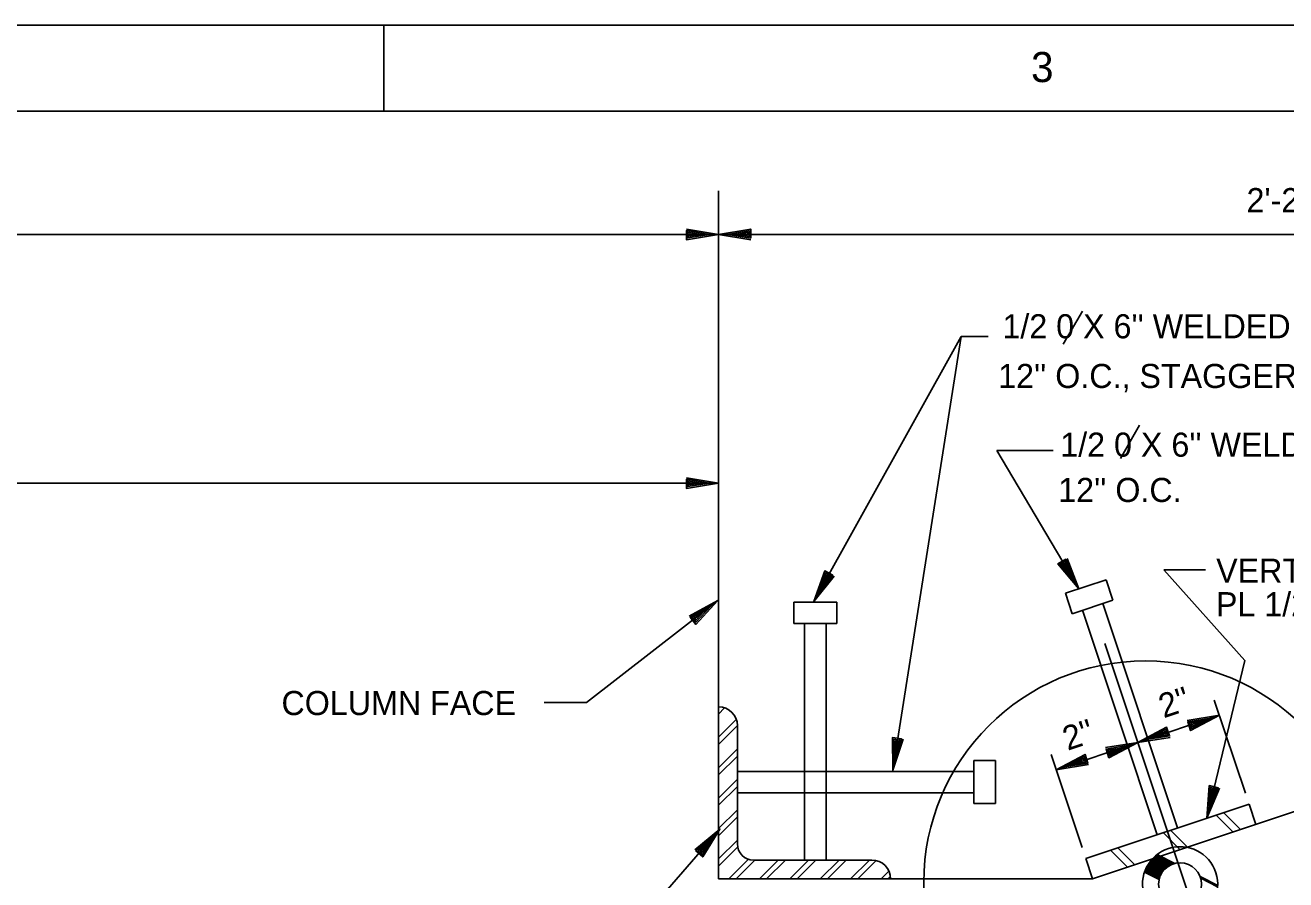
# Model space of a CAD drawing. Extents: x 0.1 to 13.5, y 0.1 to 9.5.
# Drawn here: x 4.972 to 7.414, y 7.802 to 9.458 of the extents above; entities that cross this region are included whole.
import ezdxf

# ---------------------------------------------------------------- set-up
doc = ezdxf.new("R2010")
doc.units = 0
for name, color, linetype in [('Level 1', 7, 'Continuous'), ('Level 13', 7, 'Continuous'), ('Level 25', 7, 'Continuous'), ('Level 3', 7, 'Continuous'), ('Level 36', 7, 'Continuous'), ('Level 44', 7, 'Continuous'), ('Level 50', 7, 'Continuous')]:
    doc.layers.add(name, color=color, linetype=linetype)

msp = doc.modelspace()

# ---------------------------------------------------------------- linework, layer by layer
at = {"layer": 'Level 1'}
for p, q in [((5.6667, 9.2917), (5.6667, 9.4583)), ((7.3359, 7.97), (7.2756, 8.1507)), ((7.1274, 8.0684), (7.2855, 8.1211)), ((6.9693, 8.0157), (7.1274, 8.0684)), ((7.0196, 7.8646), (6.9594, 8.0453))]:
    msp.add_line(p, q, dxfattribs=at)
for points in [[(0.125, 9.4583), (13.4583, 9.4583), (13.4583, 0.125), (0.125, 0.125)], [(0.625, 9.2917), (13.2917, 9.2917), (13.2917, 0.2917), (0.625, 0.2917)]]:
    msp.add_lwpolyline(points, close=True, dxfattribs=at)
at = {"layer": 'Level 13'}
for p, q in [((7.182, 7.825), (7.1529, 7.8399)), ((7.1842, 7.8268), (7.1547, 7.8419)), ((7.1866, 7.8285), (7.1565, 7.8439)), ((7.1893, 7.8301), (7.1584, 7.8458)), ((7.1921, 7.8316), (7.1604, 7.8477)), ((7.1953, 7.8329), (7.1625, 7.8496)), ((7.1989, 7.8339), (7.1648, 7.8514)), ((7.1686, 7.8026), (7.1403, 7.8171)), ((7.1693, 7.8052), (7.1414, 7.8194)), ((7.1701, 7.8077), (7.1421, 7.822)), ((7.1711, 7.8102), (7.1433, 7.8243)), ((7.1722, 7.8125), (7.1443, 7.8267)), ((7.1734, 7.8148), (7.1455, 7.829)), ((7.1748, 7.817), (7.1468, 7.8313)), ((7.1764, 7.8191), (7.1482, 7.8335)), ((7.1781, 7.8212), (7.1497, 7.8356)), ((7.1799, 7.8232), (7.1513, 7.8378)), ((7.2822, 7.7915), (7.248, 7.8089)), ((7.282, 7.7887), (7.2493, 7.8054))]:
    msp.add_line(p, q, dxfattribs=at)
msp.add_circle((7.2093, 7.7936), 0.0417, dxfattribs=at)
msp.add_arc((7.2093, 7.7936), 0.0729, 288, 198, dxfattribs=at)
at = {"layer": 'Level 25'}
for p, q in [((6.3151, 7.8041), (6.3151, 9.1373)), ((2.1636, 9.053), (6.3151, 9.053)), ((8.532, 9.053), (6.3151, 9.053)), ((6.983, 8.84), (7.0201, 8.9042)), ((7.0937, 8.619), (7.1308, 8.6831)), ((6.8544, 8.6339), (6.9631, 8.6339)), ((6.8544, 8.6339), (7.0134, 8.3662)), ((3.1347, 8.5712), (6.3151, 8.5712)), ((7.178, 8.4027), (7.2583, 8.4027)), ((7.178, 8.4027), (7.3344, 8.227)), ((7.0662, 8.3838), (6.9871, 8.3575)), ((7.0793, 8.3443), (7.0662, 8.3838)), ((7.0003, 8.3179), (6.9871, 8.3575)), ((6.4609, 8.2989), (6.4609, 8.3406)), ((6.5443, 8.2989), (6.5443, 8.3406)), ((7.0793, 8.3443), (7.0003, 8.3179)), ((7.2045, 7.9029), (7.0596, 8.3377)), ((7.165, 7.8897), (7.02, 8.3245)), ((6.4818, 7.8406), (6.4818, 8.2989)), ((6.5234, 7.8406), (6.5234, 8.2989)), ((7.3353, 7.4447), (7.0635, 8.2601)), ((7.3344, 8.227), (7.2613, 7.9218)), ((6.3151, 8.1235), (6.3269, 8.1353)), ((6.3151, 8.0785), (6.3494, 8.1128)), ((6.3151, 8.0646), (6.3516, 8.1011)), ((6.3151, 8.0196), (6.3516, 8.056)), ((6.3151, 8.0057), (6.3516, 8.0421)), ((7.7601, 8.0442), (7.0398, 7.8041)), ((6.3516, 8.0124), (6.8099, 8.0124)), ((6.8099, 8.0333), (6.8516, 8.0333)), ((6.3151, 7.9606), (6.3516, 7.9971)), ((6.3151, 7.9468), (6.3516, 7.9832)), ((6.3516, 7.9708), (6.8099, 7.9708)), ((6.3151, 7.9017), (6.3516, 7.9382)), ((6.8099, 7.9499), (6.8516, 7.9499)), ((7.3429, 7.949), (7.0266, 7.8436)), ((7.356, 7.9095), (7.3429, 7.949)), ((6.3151, 7.8878), (6.3516, 7.9243)), ((6.3151, 7.8428), (6.3516, 7.8793)), ((6.3151, 7.8289), (6.3525, 7.8663)), ((6.3353, 7.8041), (6.3734, 7.8422)), ((6.3492, 7.8041), (6.3857, 7.8406)), ((6.3943, 7.8041), (6.4307, 7.8406)), ((6.4081, 7.8041), (6.4446, 7.8406)), ((6.4532, 7.8041), (6.4896, 7.8406)), ((6.4671, 7.8041), (6.5035, 7.8406)), ((6.5121, 7.8041), (6.5486, 7.8406)), ((6.526, 7.8041), (6.5625, 7.8406)), ((6.571, 7.8041), (6.6075, 7.8406)), ((7.0398, 7.8041), (7.0266, 7.8436)), ((6.5849, 7.8041), (6.6201, 7.8393)), ((6.63, 7.8041), (6.6449, 7.8191)), ((6.3151, 7.8041), (7.0398, 7.8041)), ((6.6439, 7.8041), (6.648, 7.8082))]:
    msp.add_line(p, q, dxfattribs=at)
msp.add_circle((7.1424, 7.7968), 0.4297, dxfattribs=at)
at = {"layer": 'Level 3'}
for p, q in [((6.7852, 8.8549), (6.4996, 8.3415)), ((6.508, 8.3566), (6.508, 8.3566)), ((6.3003, 8.3328), (6.3003, 8.3328)), ((6.314, 8.3434), (6.314, 8.3434)), ((6.4996, 8.3415), (6.4996, 8.3415)), ((6.6526, 8.0147), (6.6526, 8.0147)), ((6.6553, 8.0319), (6.6553, 8.0319)), ((6.3177, 7.9005), (6.3177, 7.9005)), ((6.3063, 7.8874), (6.3063, 7.8874))]:
    msp.add_line(p, q, dxfattribs=at)
for points in [[(6.8374, 8.8549), (6.7852, 8.8549), (6.6526, 8.0147)], [(6.5389, 8.3909), (6.4996, 8.3415), (6.5209, 8.401), (6.5363, 8.3924), (6.508, 8.3566), (6.5225, 8.397), (6.5324, 8.3915), (6.5161, 8.3712), (6.5241, 8.3931), (6.5282, 8.3908), (6.5245, 8.3864)], [(5.9772, 8.146), (6.059, 8.146), (6.314, 8.3434)], [(6.2584, 8.3134), (6.314, 8.3434), (6.2711, 8.2971), (6.2603, 8.311), (6.3003, 8.3328), (6.2711, 8.3013), (6.2642, 8.3103), (6.2872, 8.3226), (6.2712, 8.3056), (6.2684, 8.3093), (6.2734, 8.312)], [(6.6726, 8.0747), (6.6526, 8.0147), (6.6521, 8.0779), (6.6696, 8.0752), (6.6553, 8.0319), (6.655, 8.0748), (6.6662, 8.073), (6.6579, 8.0483), (6.6579, 8.0716), (6.6625, 8.0709), (6.6606, 8.0654)], [(6.0169, 7.72), (6.1613, 7.72), (6.3177, 7.9005)], [(6.269, 7.8602), (6.3177, 7.9005), (6.2846, 7.8466), (6.2713, 7.8582), (6.3063, 7.8874), (6.2839, 7.8508), (6.2753, 7.8583), (6.2954, 7.8748), (6.2831, 7.855), (6.2796, 7.8581), (6.284, 7.8617)]]:
    msp.add_lwpolyline(points, dxfattribs=at)
at = {"layer": 'Level 36'}
for p, q in [((6.4609, 8.3406), (6.5443, 8.3406)), ((6.4609, 8.2989), (6.5443, 8.2989)), ((6.3151, 7.8041), (6.3151, 8.1374)), ((6.3516, 8.101), (6.3516, 7.8718)), ((6.8099, 8.0333), (6.8099, 7.9499)), ((6.8516, 8.0333), (6.8516, 7.9499)), ((6.3828, 7.8406), (6.612, 7.8406)), ((6.6484, 7.8041), (6.3151, 7.8041))]:
    msp.add_line(p, q, dxfattribs=at)
for centre, radius, start, end in [((6.3151, 8.101), 0.0365, 0, 90), ((6.3828, 7.8718), 0.0313, 180, 270), ((6.612, 7.8041), 0.0365, 0, 90)]:
    msp.add_arc(centre, radius, start, end, dxfattribs=at)
at = {"layer": 'Level 44'}
for p, q in [((7.3123, 7.8949), (7.2793, 7.9278)), ((7.3264, 7.8996), (7.2935, 7.9326)), ((7.2097, 7.8607), (7.1768, 7.8937)), ((7.2239, 7.8654), (7.1909, 7.8984)), ((7.1214, 7.8313), (7.0884, 7.8642)), ((7.1072, 7.8266), (7.0743, 7.8595))]:
    msp.add_line(p, q, dxfattribs=at)
at = {"layer": 'Level 50'}
for p, q in [((6.2978, 9.053), (6.2978, 9.053)), ((6.3151, 9.053), (6.3151, 9.053)), ((6.3151, 9.053), (6.3151, 9.053)), ((6.3324, 9.053), (6.3324, 9.053)), ((6.2978, 8.5712), (6.2978, 8.5712)), ((6.3151, 8.5712), (6.3151, 8.5712)), ((7.0045, 8.3811), (7.0045, 8.3811)), ((7.0134, 8.3662), (7.0134, 8.3662)), ((7.269, 8.1156), (7.269, 8.1156)), ((7.2855, 8.1211), (7.2855, 8.1211)), ((7.1109, 8.0629), (7.1109, 8.0629)), ((7.1274, 8.0684), (7.1274, 8.0684)), ((7.1274, 8.0684), (7.1274, 8.0684)), ((7.1438, 8.0739), (7.1438, 8.0739)), ((6.9693, 8.0157), (6.9693, 8.0157)), ((6.9857, 8.0212), (6.9857, 8.0212)), ((7.2654, 7.9387), (7.2654, 7.9387)), ((7.2613, 7.9218), (7.2613, 7.9218))]:
    msp.add_line(p, q, dxfattribs=at)
for points in [[(6.2528, 9.0634), (6.3151, 9.053), (6.2528, 9.0427), (6.2528, 9.0604), (6.2978, 9.053), (6.2554, 9.046), (6.2554, 9.0574), (6.2811, 9.053), (6.2581, 9.0494), (6.2581, 9.054), (6.2638, 9.053)], [(6.3774, 9.0427), (6.3151, 9.053), (6.3774, 9.0634), (6.3774, 9.0457), (6.3324, 9.053), (6.3748, 9.06), (6.3748, 9.0487), (6.3491, 9.053), (6.3721, 9.0567), (6.3721, 9.052), (6.3664, 9.053)], [(6.2528, 8.5815), (6.3151, 8.5712), (6.2528, 8.5608), (6.2528, 8.5785), (6.2978, 8.5712), (6.2554, 8.5642), (6.2554, 8.5755), (6.2811, 8.5712), (6.2581, 8.5675), (6.2581, 8.5722), (6.2638, 8.5712)], [(6.9904, 8.4251), (7.0134, 8.3662), (6.9727, 8.4146), (6.9879, 8.4236), (7.0045, 8.3811), (6.9769, 8.414), (6.9866, 8.4198), (6.996, 8.3955), (6.9811, 8.4134), (6.9851, 8.4158), (6.9872, 8.4104)], [(7.2231, 8.1112), (7.2855, 8.1211), (7.2296, 8.0916), (7.224, 8.1083), (7.269, 8.1156), (7.2311, 8.0956), (7.2275, 8.1063), (7.2532, 8.1104), (7.2326, 8.0996), (7.2311, 8.104), (7.2368, 8.1049)], [(7.1898, 8.0783), (7.1274, 8.0684), (7.1832, 8.0979), (7.1888, 8.0812), (7.1438, 8.0739), (7.1818, 8.0939), (7.1853, 8.0832), (7.1596, 8.0791), (7.1803, 8.0899), (7.1818, 8.0855), (7.1761, 8.0846)], [(7.065, 8.0585), (7.1274, 8.0684), (7.0715, 8.0389), (7.0659, 8.0556), (7.1109, 8.0629), (7.073, 8.0429), (7.0694, 8.0536), (7.0951, 8.0576), (7.0745, 8.0469), (7.073, 8.0513), (7.0787, 8.0522)], [(7.0317, 8.0256), (6.9693, 8.0157), (7.0251, 8.0452), (7.0307, 8.0284), (6.9857, 8.0212), (7.0237, 8.0412), (7.0272, 8.0304), (7.0015, 8.0264), (7.0222, 8.0372), (7.0237, 8.0328), (7.018, 8.0319)], [(7.2859, 7.98), (7.2613, 7.9218), (7.2658, 7.9849), (7.283, 7.9807), (7.2654, 7.9387), (7.2684, 7.9815), (7.2794, 7.9789), (7.2692, 7.9549), (7.271, 7.9781), (7.2756, 7.977), (7.2733, 7.9718)]]:
    msp.add_lwpolyline(points, dxfattribs=at)

# ---------------------------------------------------------------- texts
at = {"layer": 'Level 1'}
for s, height, p in [('3', 0.0584, (6.9206, 9.3481)), ('2\'-2 1/4"', 0.0467, (7.338, 9.096)), ("1/2 0 X 6'' WELDED ANCHORS,", 0.046698, (6.8651, 8.8516)), ("12'' O.C., STAGGERED", 0.046698, (6.8568, 8.7553)), ("1/2 0 X 6'' WELDED ANCHORS,", 0.046698, (6.9772, 8.6222)), ("12'' O.C.", 0.0467, (6.9732, 8.5344)), ('VERTICAL SEAL', 0.046698, (7.2792, 8.378)), ('PL 1/2X4, C.R.S.', 0.046698, (7.2787, 8.313)), ('COLUMN FACE', 0.046698, (5.4683, 8.1215))]:
    msp.add_text(s, height=height, dxfattribs=at).set_placement(p)
for p in [(7.1774, 8.1151), (6.9914, 8.0523)]:
    msp.add_text("2''", height=0.0467, rotation=18.4361, dxfattribs=at).set_placement(p)

doc.saveas('drawing.dxf')
